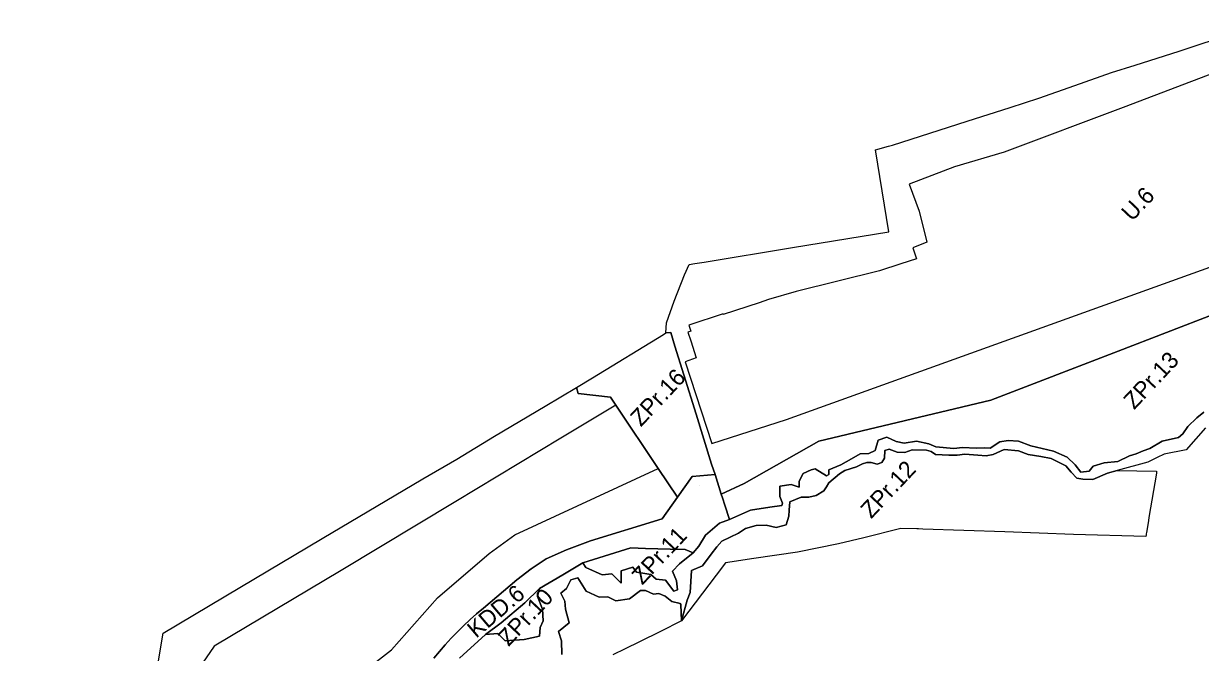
# Model space of a CAD drawing. Extents: x 7425782 to 7428854, y 5550411 to 5553074.
# Drawn here: x 7426991 to 7427625, y 5551702 to 5552041 of the extents above; entities that cross this region are included whole.
import ezdxf

# ---------------------------------------------------------------- set-up
doc = ezdxf.new("R2010")
doc.units = 0
for name, color, linetype in [('LIN_linie_rozgraniczajace', 7, 'Continuous'), ('LIN_nieprzekraczalna linia zabudowy', 7, 'Continuous'), ('TXT_oznaczenia przeznaczen', 7, 'Continuous')]:
    doc.layers.add(name, color=color, linetype=linetype)

msp = doc.modelspace()

# ---------------------------------------------------------------- linework, layer by layer
at = {"layer": 'LIN_linie_rozgraniczajace'}
for points in [[(7427659.08, 5551894.5), (7427580.93, 5551864.35), (7427512.4, 5551837.87), (7427419.71, 5551815.85), (7427379.52, 5551793.04), (7427367.09, 5551787.27), (7427363.81, 5551797.95), (7427361.81, 5551803.51), (7427353.56, 5551830.41), (7427346.95, 5551851.51), (7427342.01, 5551867.02), (7427339.88, 5551874.38), (7427337.29, 5551874.18), (7427337.64, 5551879.67), (7427341.72, 5551891.34), (7427347.36, 5551905.38), (7427349.76, 5551911.05), (7427352.86, 5551911.53), (7427357.88, 5551912.33), (7427405.53, 5551920.16), (7427457.39, 5551928.67), (7427450.26, 5551972.74), (7427457.14, 5551974.84), (7427459.44, 5551975.39), (7427499.65, 5551988.24), (7427522.81, 5551995.58), (7427538.17, 5552000.63), (7427557.67, 5552007.54), (7427577.43, 5552014.55), (7427590.12, 5552018.41), (7427613.76, 5552026.04), (7427625.13, 5552029.74), (7427647.14, 5552036.9)], [(7427627.12, 5551831.5), (7427623.33, 5551828.36), (7427618.47, 5551823.76), (7427615.69, 5551819.87), (7427613.41, 5551817.8), (7427604.6, 5551815.83), (7427598.02, 5551811.96), (7427594.43, 5551810.63), (7427590.62, 5551808.98), (7427586.96, 5551807.98), (7427580.67, 5551804.92), (7427573.42, 5551804.23), (7427567.47, 5551802.44), (7427565.34, 5551799.74), (7427560.75, 5551799.17), (7427557.73, 5551803.17), (7427553.46, 5551807.26), (7427546.1, 5551810.53), (7427533.81, 5551813.37), (7427527.19, 5551815.86), (7427521.62, 5551816.15), (7427517.19, 5551815.47), (7427512.04, 5551812.16), (7427508.7, 5551812.29), (7427504.44, 5551812.06), (7427497.11, 5551812.45), (7427492.44, 5551811.85), (7427482.73, 5551812.74), (7427478.94, 5551814.47), (7427472.35, 5551815.89), (7427465.71, 5551814.75), (7427461.25, 5551815.7), (7427456.25, 5551817.97), (7427451.56, 5551816.43), (7427450.09, 5551810.84), (7427446.65, 5551809.21), (7427441.97, 5551809.04), (7427437.32, 5551806.3), (7427431.47, 5551803.15), (7427424.98, 5551800.4), (7427425.01, 5551797.82), (7427423.82, 5551797.26), (7427417.73, 5551800.93), (7427415.5, 5551800.36), (7427411.15, 5551798.49), (7427409.11, 5551794.31), (7427409.08, 5551790.99), (7427404.72, 5551792.43), (7427398.72, 5551791.55), (7427398.63, 5551786.05), (7427400.14, 5551782.48), (7427399.66, 5551781.17), (7427393.35, 5551780.24), (7427382.83, 5551778.72), (7427371.49, 5551773.58), (7427369.02, 5551781.35), (7427367.69, 5551785.31), (7427367.09, 5551787.27), (7427379.52, 5551793.04), (7427419.71, 5551815.85), (7427512.4, 5551837.87), (7427580.93, 5551864.35), (7427659.08, 5551894.5)], [(7427062.95, 5551692.14), (7427066.49, 5551712.37), (7427107.74, 5551736.97), (7427152.12, 5551763.38), (7427206.26, 5551795.5), (7427224.69, 5551806.13), (7427244.9, 5551818.58), (7427272.17, 5551834.63), (7427289.1, 5551844.77), (7427290.1, 5551841.54), (7427307.38, 5551839.57), (7427310.23, 5551835.33), (7427333.15, 5551801.19), (7427343.55, 5551785.7), (7427335.33, 5551774.08), (7427296.68, 5551762.12), (7427283.8, 5551757.26), (7427272.82, 5551752.44), (7427264.68, 5551747.04), (7427257.01, 5551741.08), (7427238.95, 5551725.98), (7427235.33, 5551722.89), (7427231.79, 5551719.71), (7427228.33, 5551716.45), (7427224.94, 5551713.11), (7427221.63, 5551709.69), (7427218.4, 5551706.2), (7427215.26, 5551702.62), (7427212.2, 5551698.98)], [(7427226.11, 5551698.89), (7427240.05, 5551711.78), (7427246.7, 5551712.18), (7427250.65, 5551708.22), (7427261, 5551709.04), (7427269.22, 5551710.73), (7427269.48, 5551715.4), (7427271.16, 5551719.02), (7427270.85, 5551725.44), (7427268.1, 5551732.18), (7427269.11, 5551736.53), (7427281.76, 5551743.76), (7427292.57, 5551750.35), (7427294.2, 5551747.84), (7427303.01, 5551743.81), (7427308.1, 5551744.32), (7427313.24, 5551739.34), (7427313.16, 5551745.96), (7427319.55, 5551747.99), (7427321.46, 5551745.37), (7427324.87, 5551744.82), (7427329.1, 5551744.04), (7427332.05, 5551741.49), (7427337.1, 5551740.97), (7427341.57, 5551735.01), (7427343.53, 5551735.83), (7427342.94, 5551740.6), (7427340.92, 5551745.85), (7427344.56, 5551749.76), (7427352.01, 5551755.63), (7427355.08, 5551759.25), (7427358.64, 5551765.19), (7427366.09, 5551771.65), (7427371.49, 5551773.58), (7427382.83, 5551778.72), (7427393.35, 5551780.24), (7427399.66, 5551781.17), (7427400.14, 5551782.48), (7427398.63, 5551786.05), (7427398.72, 5551791.55), (7427404.72, 5551792.43), (7427409.08, 5551790.99), (7427409.11, 5551794.31), (7427411.15, 5551798.49), (7427415.5, 5551800.36), (7427417.73, 5551800.93), (7427423.82, 5551797.26), (7427425.01, 5551797.82), (7427424.98, 5551800.4), (7427431.47, 5551803.15), (7427437.32, 5551806.3), (7427441.97, 5551809.04), (7427446.65, 5551809.21), (7427450.09, 5551810.84), (7427451.56, 5551816.43), (7427456.25, 5551817.97), (7427461.25, 5551815.7), (7427465.71, 5551814.75), (7427472.35, 5551815.89), (7427478.94, 5551814.47), (7427482.73, 5551812.74), (7427492.44, 5551811.85), (7427497.11, 5551812.45), (7427504.44, 5551812.06), (7427508.7, 5551812.29), (7427512.04, 5551812.16), (7427517.19, 5551815.47), (7427521.62, 5551816.15), (7427527.19, 5551815.86), (7427533.81, 5551813.37), (7427546.1, 5551810.53), (7427553.46, 5551807.26), (7427557.73, 5551803.17), (7427560.75, 5551799.17), (7427565.34, 5551799.74), (7427567.47, 5551802.44), (7427573.42, 5551804.23), (7427580.67, 5551804.92), (7427586.96, 5551807.98), (7427590.62, 5551808.98), (7427594.43, 5551810.63), (7427598.02, 5551811.96), (7427604.6, 5551815.83), (7427613.41, 5551817.8), (7427615.69, 5551819.87), (7427618.47, 5551823.76), (7427623.33, 5551828.36), (7427627.12, 5551831.5)], [(7427628.07, 5551822.99), (7427617.6, 5551811.23), (7427605.66, 5551808.89), (7427601.89, 5551807.01), (7427596.95, 5551804.55), (7427580.47, 5551800.03), (7427580.45, 5551800.03), (7427575.2, 5551798.7), (7427567.21, 5551795.2), (7427561.95, 5551795.39), (7427558.63, 5551795.99), (7427555.57, 5551799.21), (7427552.71, 5551802.63), (7427548.79, 5551804.48), (7427544.93, 5551806.48), (7427539.27, 5551807.54), (7427532.46, 5551808.71), (7427527.19, 5551810.7), (7427519.61, 5551811.38), (7427513.67, 5551808.66), (7427509.8, 5551807.94), (7427505.32, 5551808.29), (7427498.33, 5551808.92), (7427494.13, 5551808.33), (7427489.72, 5551808.31), (7427482.46, 5551808.67), (7427480.14, 5551810.26), (7427477.71, 5551811.1), (7427470.04, 5551811.18), (7427466.03, 5551809.84), (7427461.82, 5551810.01), (7427457.58, 5551811.56), (7427455.17, 5551810.88), (7427455, 5551806.66), (7427453.7, 5551804.39), (7427451.04, 5551803.44), (7427447.85, 5551804.32), (7427445.58, 5551804.3), (7427443.17, 5551803.69), (7427440.04, 5551801.97), (7427433.69, 5551800.12), (7427430.82, 5551798.34), (7427425.08, 5551793.45), (7427423.85, 5551791.26), (7427422.32, 5551789.11), (7427418.3, 5551786.53), (7427414.36, 5551785.63), (7427410.12, 5551785.76), (7427404.06, 5551783.1), (7427403.67, 5551778.68), (7427403.56, 5551775.53), (7427402.04, 5551770.81), (7427396.77, 5551769.27), (7427391.23, 5551770.6), (7427385.97, 5551770.42), (7427380.16, 5551768.83), (7427376.44, 5551766.37), (7427367.33, 5551761.98), (7427364.68, 5551758.93), (7427361.71, 5551755.04), (7427357.04, 5551748.61), (7427351.12, 5551746.23), (7427350.27, 5551734.38), (7427348.74, 5551730.12), (7427345.72, 5551719.01), (7427345.34, 5551727.88), (7427344.98, 5551728.4), (7427340.45, 5551729.4), (7427336.87, 5551732.36), (7427333.5, 5551733.74), (7427330.52, 5551733.37), (7427326.32, 5551735.42), (7427323.54, 5551735.37), (7427317.62, 5551730.84), (7427310.28, 5551729.82), (7427305.95, 5551732.03), (7427301.38, 5551731.85), (7427294.31, 5551735.12), (7427289.9, 5551742.22), (7427286.12, 5551741.1), (7427283.81, 5551736.44), (7427280.65, 5551733.92), (7427282.85, 5551729.68), (7427283.11, 5551725.42), (7427285.17, 5551717.91), (7427279.36, 5551713.24), (7427281.08, 5551708.22), (7427281.22, 5551700.92)], [(7427212.2, 5551698.98), (7427215.26, 5551702.62), (7427218.4, 5551706.2), (7427221.63, 5551709.69), (7427224.94, 5551713.11), (7427228.33, 5551716.45), (7427231.79, 5551719.71), (7427235.33, 5551722.89), (7427238.95, 5551725.98), (7427257.01, 5551741.08), (7427264.68, 5551747.04), (7427272.82, 5551752.44), (7427283.8, 5551757.26), (7427296.68, 5551762.12), (7427335.33, 5551774.08), (7427343.55, 5551785.7), (7427351.48, 5551796.91), (7427363.81, 5551797.95), (7427367.09, 5551787.27), (7427367.69, 5551785.31), (7427369.02, 5551781.35), (7427371.49, 5551773.58), (7427366.09, 5551771.65), (7427358.64, 5551765.19), (7427355.08, 5551759.25), (7427352.01, 5551755.63), (7427347.73, 5551757.57), (7427339.58, 5551757.76), (7427326.29, 5551757.99), (7427318.37, 5551758.33), (7427292.57, 5551750.35), (7427281.76, 5551743.76), (7427269.11, 5551736.53), (7427261.26, 5551728.85), (7427248.48, 5551717.9), (7427240.05, 5551711.78), (7427226.11, 5551698.89)], [(7427281.22, 5551700.92), (7427281.08, 5551708.22), (7427279.36, 5551713.24), (7427285.17, 5551717.91), (7427283.11, 5551725.42), (7427282.85, 5551729.68), (7427280.65, 5551733.92), (7427283.81, 5551736.44), (7427286.12, 5551741.1), (7427289.9, 5551742.22), (7427294.31, 5551735.12), (7427301.38, 5551731.85), (7427305.95, 5551732.03), (7427310.28, 5551729.82), (7427317.62, 5551730.84), (7427323.54, 5551735.37), (7427326.32, 5551735.42), (7427330.52, 5551733.37), (7427333.5, 5551733.74), (7427336.87, 5551732.36), (7427340.45, 5551729.4), (7427344.98, 5551728.4), (7427345.34, 5551727.88), (7427345.72, 5551719.01), (7427334.38, 5551713.39), (7427323.03, 5551707.78), (7427315.31, 5551703.95), (7427308.73, 5551700.68)]]:
    msp.add_lwpolyline(points, dxfattribs=at)
for points in [[(7427363.81, 5551797.95), (7427351.48, 5551796.91), (7427343.55, 5551785.7), (7427333.15, 5551801.19), (7427310.23, 5551835.33), (7427307.38, 5551839.57), (7427290.1, 5551841.54), (7427289.1, 5551844.77), (7427297.75, 5551849.94), (7427335.93, 5551873.35), (7427337.29, 5551874.18), (7427339.88, 5551874.38), (7427342.01, 5551867.02), (7427346.95, 5551851.51), (7427353.56, 5551830.41), (7427361.81, 5551803.51)], [(7427461.82, 5551810.01), (7427466.03, 5551809.84), (7427470.04, 5551811.18), (7427477.71, 5551811.1), (7427480.14, 5551810.26), (7427482.46, 5551808.67), (7427489.72, 5551808.31), (7427494.13, 5551808.33), (7427498.33, 5551808.92), (7427505.32, 5551808.29), (7427509.8, 5551807.94), (7427513.67, 5551808.66), (7427519.61, 5551811.38), (7427527.19, 5551810.7), (7427532.46, 5551808.71), (7427539.27, 5551807.54), (7427544.93, 5551806.48), (7427548.79, 5551804.48), (7427552.71, 5551802.63), (7427555.57, 5551799.21), (7427558.63, 5551795.99), (7427561.95, 5551795.39), (7427567.21, 5551795.2), (7427575.2, 5551798.7), (7427580.45, 5551800.03), (7427601.67, 5551799.72), (7427601.67, 5551799.72), (7427601.5, 5551798.69), (7427597.52, 5551774.72), (7427597.5, 5551774.58), (7427597.05, 5551771.83), (7427596.19, 5551766.68), (7427596.06, 5551765.88), (7427596, 5551765.26), (7427595.91, 5551764.49), (7427595.91, 5551764.49), (7427556.8, 5551765.66), (7427519.86, 5551767), (7427475.7, 5551768.52), (7427473.36, 5551768.6), (7427473.36, 5551768.6), (7427472.56, 5551768.62), (7427463.91, 5551768.84), (7427443.89, 5551763.86), (7427430.21, 5551760.46), (7427408.22, 5551756.14), (7427384.73, 5551752.57), (7427369.37, 5551750.23), (7427364.37, 5551743.64), (7427345.72, 5551719.01), (7427348.74, 5551730.12), (7427350.27, 5551734.38), (7427351.12, 5551746.23), (7427357.04, 5551748.61), (7427361.71, 5551755.04), (7427364.68, 5551758.93), (7427367.33, 5551761.98), (7427376.44, 5551766.37), (7427380.16, 5551768.83), (7427385.97, 5551770.42), (7427391.23, 5551770.6), (7427396.77, 5551769.27), (7427402.04, 5551770.81), (7427403.56, 5551775.53), (7427403.67, 5551778.68), (7427404.06, 5551783.1), (7427410.12, 5551785.76), (7427414.36, 5551785.63), (7427418.3, 5551786.53), (7427422.32, 5551789.11), (7427423.85, 5551791.26), (7427425.08, 5551793.45), (7427430.82, 5551798.34), (7427433.69, 5551800.12), (7427440.04, 5551801.97), (7427443.17, 5551803.69), (7427445.58, 5551804.3), (7427447.85, 5551804.32), (7427451.04, 5551803.44), (7427453.7, 5551804.39), (7427455, 5551806.66), (7427455.17, 5551810.88), (7427457.58, 5551811.56)], [(7427352.01, 5551755.63), (7427344.56, 5551749.76), (7427340.92, 5551745.85), (7427342.94, 5551740.6), (7427343.53, 5551735.83), (7427341.57, 5551735.01), (7427337.1, 5551740.97), (7427332.05, 5551741.49), (7427329.1, 5551744.04), (7427324.87, 5551744.82), (7427321.46, 5551745.37), (7427319.55, 5551747.99), (7427313.16, 5551745.96), (7427313.24, 5551739.34), (7427308.1, 5551744.32), (7427303.01, 5551743.81), (7427294.2, 5551747.84), (7427292.57, 5551750.35), (7427318.37, 5551758.33), (7427326.29, 5551757.99), (7427339.58, 5551757.76), (7427347.73, 5551757.57)], [(7427240.05, 5551711.78), (7427248.48, 5551717.9), (7427261.26, 5551728.85), (7427269.11, 5551736.53), (7427268.1, 5551732.18), (7427270.85, 5551725.44), (7427271.16, 5551719.02), (7427269.48, 5551715.4), (7427269.22, 5551710.73), (7427261, 5551709.04), (7427250.65, 5551708.22), (7427246.7, 5551712.18)]]:
    msp.add_lwpolyline(points, close=True, dxfattribs=at)
at = {"layer": 'LIN_nieprzekraczalna linia zabudowy'}
msp.add_line((7427355.26, 5551791.81), (7427355.26, 5551791.81), dxfattribs=at)
for points in [[(7427362.07, 5551814.56), (7427402.21, 5551827.55), (7427743.05, 5551950.14), (7427750.05, 5552028.23), (7427729.2, 5552040.85)], [(7427729.2, 5552040.85), (7427638.52, 5552011.24), (7427636.88, 5552015.96), (7427583.69, 5551995.55), (7427519.59, 5551971.59), (7427492.84, 5551963.62), (7427468.35, 5551954.25), (7427473.77, 5551939.85), (7427477.77, 5551923.1), (7427470.24, 5551920.05), (7427472.36, 5551914.12)], [(7427472.36, 5551914.12), (7427463.94, 5551911.48), (7427452.4, 5551907.6), (7427407.46, 5551896.55), (7427392.54, 5551892.26), (7427387.49, 5551890.47), (7427368.21, 5551884.16), (7427368.09, 5551884.5)], [(7427368.09, 5551884.5), (7427349.7, 5551878.39), (7427350.72, 5551875.13), (7427349.06, 5551874.58), (7427350.64, 5551869.83), (7427353.62, 5551860.7), (7427347.68, 5551858.63), (7427362.07, 5551814.56)], [(7427310.23, 5551835.33), (7427298.58, 5551828.29), (7427280.76, 5551817.51), (7427224.2, 5551783.28)], [(7427242.1, 5551755.43), (7427255.89, 5551765.47), (7427333.15, 5551801.19)], [(7427224.2, 5551783.28), (7427162.34, 5551746.19), (7427094, 5551705.47), (7427045.17, 5551634.42), (7427039.46, 5551628.26), (7427011.8, 5551595.49), (7427005.05, 5551588.21), (7426991.22, 5551563.06), (7426993.16, 5551561.88)], [(7426993.16, 5551561.88), (7427025.17, 5551543.48), (7427037.06, 5551537.1), (7427068.53, 5551571.17), (7427085.36, 5551594.5), (7427098.17, 5551608.93), (7427110.43, 5551620.01), (7427120.9, 5551628.57), (7427117.16, 5551634.81), (7427110.82, 5551645.31), (7427142.46, 5551666.72), (7427189.47, 5551703.52), (7427214.29, 5551731.49), (7427242.1, 5551755.43)]]:
    msp.add_lwpolyline(points, dxfattribs=at)

# ---------------------------------------------------------------- texts
at = {"layer": 'TXT_oznaczenia przeznaczen'}
for s, rotation, p in [('U.6', 46.77361, (7427588.4, 5551933.85)), ('ZPr.13', 46.77361, (7427589.56, 5551832.5)), ('ZPr.16', 46.77361, (7427323.84, 5551823.25)), ('ZPr.12', 46.77361, (7427447.89, 5551773.75)), ('ZPr.11', 46.77361, (7427324.58, 5551738.03)), ('KDD.6', 40.3659, (7427235.03, 5551709.39)), ('ZPr.10', 46.77361, (7427252.53, 5551704.88))]:
    msp.add_text(s, height=9, rotation=rotation, dxfattribs=at).set_placement(p)

doc.saveas('drawing.dxf')
